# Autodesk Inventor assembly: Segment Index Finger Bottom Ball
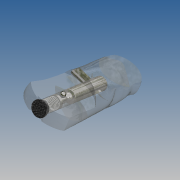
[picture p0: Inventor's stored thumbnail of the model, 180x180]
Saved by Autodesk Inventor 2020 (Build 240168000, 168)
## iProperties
Created: 2019-10
Part Number: Segment Index Finger Bottom Ball
Document SubType Name: Assembly
Designer: yello
Author: yello
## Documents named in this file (7)
- C:\Users\yello\Documents\Mechanical Hand\Prototype 2 (Realistic Hand)\Segment Index Finger Bottom Ball.iam
- C:\Users\yello\Documents\Mechanical Hand\Prototype 2 (Realistic Hand)\Segment Index Finger Bottom.ipt
- C:\Users\yello\Documents\Mechanical Hand\Prototype 2 (Realistic Hand)\Push Part.ipt
- C:\Users\yello\Documents\Mechanical Hand\Prototype 2 (Realistic Hand)\Plug.ipt
- C:\Users\yello\Documents\Mechanical Hand\Prototype 2 (Realistic Hand)\Spring.ipt
- C:\Users\yello\Documents\Mechanical Hand\Prototype 2 (Realistic Hand)\Ball.ipt
- C:\Users\yello\Documents\Mechanical Hand\Prototype 2 (Realistic Hand)\Lock.ipt
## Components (7 placed, 6 different names)
1. Segment Index Finger Bottom:1 — Mate:1, Mate:2, Mate:3, Mate:5, Mate:6, Mate:7, Mate:10
2. Push Part:1 — Mate:1, Mate:8, Mate:9
3. Plug:1 — Mate:2, Mate:3
4. Spring:1 — Mate:5
5. Ball:1 — Mate:6
6. Ball:2 — Mate:7
7. Lock:1 — Mate:8, Mate:9, Mate:10
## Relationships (9: Mate 9)
- Mate:1: Segment Index Finger Bottom:1 ↔ Push Part:1
- Mate:2: Segment Index Finger Bottom:1 ↔ Plug:1
- Mate:3: Segment Index Finger Bottom:1 ↔ Plug:1
- Mate:5: Segment Index Finger Bottom:1 ↔ Spring:1
- Mate:6: Segment Index Finger Bottom:1 ↔ Ball:1
- Mate:7: Segment Index Finger Bottom:1 ↔ Ball:2
- Mate:8: Push Part:1 ↔ Lock:1
- Mate:9: Push Part:1 ↔ Lock:1
- Mate:10: Segment Index Finger Bottom:1 ↔ Lock:1
